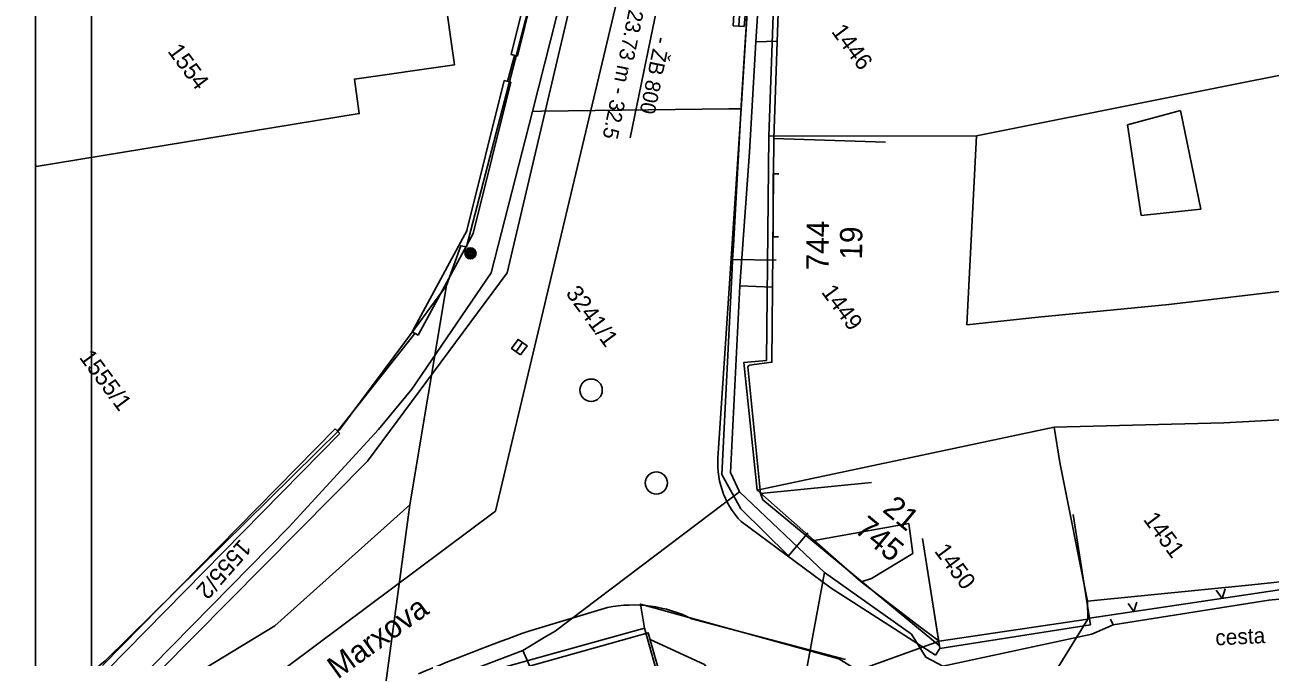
# Model space of a CAD drawing. Extents: x -601580 to 4, y -1204314 to 4.
# Drawn here: x -596076.5 to -596020.7, y -1203028.4 to -1203000.1 of the extents above; entities that cross this region are included whole.
import ezdxf

# ---------------------------------------------------------------- set-up
doc = ezdxf.new("R2010")
doc.units = 0
for name, color, linetype in [('00-INNOGY-STL', 7, 'Continuous'), ('00-KN-HRANICE PARCEL', 7, 'Continuous'), ('00-KN-PARC. CISLA', 7, 'Continuous'), ('00-KN-VNITRNI KRESBA', 7, 'Continuous'), ('00-POLOHOPIS', 7, 'Continuous'), ('00-RAZÍTKO', 7, 'Continuous'), ('00-SITE KOM. KABEL', 7, 'Continuous'), ('00-VAK-KANAL-POPIS', 7, 'Continuous'), ('00-VAK-KANAL-POTRUBI', 7, 'Continuous'), ('00-VAK-VODA-RAD IGIS', 7, 'Continuous'), ('Vrstva 25', 7, 'Continuous'), ('Vrstva 27', 7, 'Continuous'), ('Vrstva 6', 7, 'Continuous')]:
    doc.layers.add(name, color=color, linetype=linetype)

# ---------------------------------------------------------------- blocks, each defined once
blk = doc.blocks.new('6.20_34')
at = {"layer": 'Vrstva 27'}
blk.add_circle((0, 0), 0.5, dxfattribs=at)
blk = doc.blocks.new('6.20_36')
at = {"layer": 'Vrstva 27'}
blk.add_circle((0, 0), 0.5, dxfattribs=at)
blk = doc.blocks.new('6.30_32')
at = {"layer": 'Vrstva 27'}
blk.add_line((-0.25, 0), (0.25, 0), dxfattribs=at)
blk.add_lwpolyline([(-0.25, -0.25), (0.25, -0.25), (0.25, 0.25), (-0.25, 0.25)], close=True, dxfattribs=at)
blk = doc.blocks.new('6.30_36')
at = {"layer": 'Vrstva 27'}
blk.add_line((-0.25, 0), (0.25, 0), dxfattribs=at)
blk.add_lwpolyline([(-0.25, -0.249), (0.249, -0.25), (0.25, 0.249), (-0.249, 0.25)], close=True, dxfattribs=at)
blk = doc.blocks.new('6.01A_948')
at = {"layer": 'Vrstva 25'}
for radius in [0.25, 0.2, 0.15, 0.1, 0.05]:
    blk.add_circle((0, 0), radius, dxfattribs=at)
blk = doc.blocks.new('VCHOD_1784')
at = {"layer": 'Vrstva 6'}
blk.add_line((0, 0.25), (0, 0), dxfattribs=at)
blk = doc.blocks.new('VCHOD_1786')
at = {"layer": 'Vrstva 6'}
blk.add_line((0, 0.25), (0, 0), dxfattribs=at)

msp = doc.modelspace()

# ---------------------------------------------------------------- linework, layer by layer
for points in [[(-595970.972, -1202892.468), (-595970.972, -1202889.968), (-596076.023, -1202889.968), (-596076.023, -1203038.468), (-595970.972, -1203038.468), (-595970.972, -1203035.968)], [(-595973.472, -1202892.468), (-596073.523, -1202892.468), (-596073.523, -1203035.968), (-595973.472, -1203035.968)]]:
    msp.add_lwpolyline(points)
at = {"layer": '00-INNOGY-STL'}
msp.add_line((-596044.786, -1203010.608), (-596042.83, -1203010.626), dxfattribs=at)
for points in [[(-596076.023, -1203034.145), (-596064.674, -1203022.605), (-596060.652, -1203018.225), (-596059.161, -1203016.409), (-596055.603, -1203011.202), (-596053.753, -1203003.963), (-596051.597, -1202995.476), (-596051.393, -1202994.341), (-596050.742, -1202990.856), (-596050.738, -1202990.835), (-596049.188, -1202984.024), (-596049.13, -1202983.918), (-596049.061, -1202983.842), (-596046.948, -1202982.697), (-596046.863, -1202982.659), (-596046.815, -1202982.524), (-596045.335, -1202977.689), (-596043.643, -1202967.753), (-596042.334, -1202958.612), (-596041.394, -1202951.724), (-596041.232, -1202950.533), (-596041.005, -1202949.373)], [(-596042.353, -1202992.662), (-596042.645, -1202992.654), (-596043.705, -1202992.619), (-596044.399, -1203003.703), (-596044.409, -1203003.852)], [(-596053.753, -1203003.963), (-596053.359, -1203003.957), (-596044.953, -1203003.857), (-596044.409, -1203003.852)], [(-596044.409, -1203003.852), (-596044.417, -1203004.008), (-596044.751, -1203009.984), (-596044.786, -1203010.608)], [(-596044.786, -1203010.608), (-596044.806, -1203011.034), (-596045.274, -1203020.236), (-596044.424, -1203021.784), (-596042.276, -1203023.889), (-596041.685, -1203023.176), (-596041.415, -1203022.851)]]:
    msp.add_lwpolyline(points, dxfattribs=at)
at = {"layer": '00-KN-HRANICE PARCEL'}
for p, q in [((-596043.16, -1203005.08), (-596042.701, -1202991.638)), ((-596059.256, -1203021.598), (-596057.615, -1203011.762)), ((-596030.379, -1203018.122), (-596022.766, -1203017.926)), ((-596022.766, -1203017.926), (-596017.692, -1203017.647)), ((-596043.691, -1203020.942), (-596030.379, -1203018.122)), ((-596059.256, -1203021.598), (-596060.432, -1203030.367)), ((-596028.879, -1203025.913), (-596028.863, -1203026.723)), ((-596028.863, -1203026.723), (-596035.536, -1203027.716)), ((-596028.863, -1203026.723), (-596031.071, -1203030.292)), ((-596060.432, -1203030.367), (-596048.738, -1203027.129)), ((-596039.175, -1203029.022), (-596035.536, -1203027.716))]:
    msp.add_line(p, q, dxfattribs=at)
for points in [[(-596057.615, -1203011.762), (-596056.967, -1203009.986), (-596056.717, -1203010.037), (-596053.589, -1202998.026), (-596052.638, -1202993.435)], [(-596076.005, -1203006.433), (-596061.523, -1203004.065), (-596061.738, -1203002.518), (-596057.246, -1203001.874), (-596058.195, -1202995.243), (-596076.023, -1202997.797)], [(-596013.132, -1203001.173), (-596017.019, -1203001.692), (-596033.864, -1203005.054), (-596043.16, -1203005.08)], [(-596043.16, -1203005.08), (-596043.266, -1203015.122), (-596044.288, -1203015.221), (-596043.691, -1203020.942)], [(-596076.023, -1203006.312), (-596076.005, -1203006.433)], [(-596076.023, -1203031.127), (-596072.907, -1203028.593), (-596062.412, -1203018.237), (-596059.007, -1203013.68), (-596057.615, -1203011.762)], [(-596030.379, -1203018.122), (-596030.119, -1203019.697), (-596028.879, -1203025.913)], [(-596039.031, -1203025.055), (-596041.136, -1203023.192), (-596043.691, -1203020.942)], [(-596076.504, -1203033.529), (-596075.203, -1203033.049), (-596065.305, -1203027.022), (-596059.256, -1203021.598)], [(-596028.879, -1203025.913), (-596021.51, -1203025.188), (-596017.58, -1203024.761)], [(-596035.536, -1203027.716), (-596036.527, -1203026.969), (-596039.031, -1203025.055)], [(-596039.175, -1203029.022), (-596040.02, -1203028.504), (-596048.92, -1203026.044), (-596048.738, -1203027.129)], [(-596048.738, -1203027.129), (-596047.655, -1203030.97), (-596045.714, -1203038.148), (-596045.608, -1203038.468)]]:
    msp.add_lwpolyline(points, dxfattribs=at)
at = {"layer": '00-KN-VNITRNI KRESBA'}
for p, q in [((-596024.712, -1203003.928), (-596027.093, -1203004.562)), ((-596023.808, -1203008.35), (-596024.712, -1203003.928)), ((-596027.093, -1203004.562), (-596026.48, -1203008.627)), ((-596033.864, -1203005.054), (-596034.296, -1203013.532)), ((-596026.48, -1203008.627), (-596023.808, -1203008.35)), ((-596025.239, -1203012.613), (-596018.343, -1203011.803)), ((-596031.1, -1203013.19), (-596025.239, -1203012.613)), ((-596034.296, -1203013.532), (-596031.1, -1203013.19)), ((-596041.136, -1203023.192), (-596036.884, -1203022.428)), ((-596036.884, -1203022.428), (-596036.705, -1203023.776)), ((-596036.705, -1203023.776), (-596038.559, -1203024.903)), ((-596038.559, -1203024.903), (-596039.031, -1203025.055))]:
    msp.add_line(p, q, dxfattribs=at)
at = {"layer": '00-POLOHOPIS'}
for p, q in [((-596043.41, -1202988.348), (-596044.392, -1203003.626)), ((-596054.714, -1203001.418), (-596052.926, -1202994.164)), ((-596054.423, -1203001.49), (-596052.635, -1202994.236)), ((-596054.894, -1203011.196), (-596051.632, -1202997.343)), ((-596054.88, -1203002.622), (-596054.567, -1203001.454)), ((-596054.714, -1203001.418), (-596054.423, -1203001.49)), ((-596056.708, -1203009.361), (-596055.025, -1203002.587)), ((-596056.416, -1203009.434), (-596054.733, -1203002.659)), ((-596055.025, -1203002.587), (-596054.733, -1203002.659)), ((-596045.428, -1203019.284), (-596044.392, -1203003.626)), ((-596042.975, -1203009.593), (-596042.971, -1203006.764)), ((-596059.147, -1203013.851), (-596056.68, -1203009.291)), ((-596058.883, -1203013.994), (-596056.416, -1203009.434)), ((-596061.155, -1203019.641), (-596054.894, -1203011.196)), ((-596062.499, -1203018.29), (-596059.022, -1203013.918)), ((-596059.147, -1203013.851), (-596058.883, -1203013.994)), ((-596073.029, -1203028.801), (-596062.602, -1203018.188)), ((-596072.815, -1203029.012), (-596062.389, -1203018.398)), ((-596062.602, -1203018.188), (-596062.389, -1203018.398)), ((-596070.476, -1203029.047), (-596061.155, -1203019.641)), ((-596043.425, -1203021.379), (-596043.544, -1203021.094)), ((-596040.375, -1203025.333), (-596044.404, -1203022.348)), ((-596035.691, -1203028.334), (-596040.372, -1203025.326)), ((-596053.923, -1203027.254), (-596050.392, -1203026.198)), ((-596046.614, -1203026.702), (-596039.726, -1203028.53)), ((-596035.502, -1203028.039), (-596035.691, -1203028.334))]:
    msp.add_line(p, q, dxfattribs=at)
for points in [[(-596037.935, -1203005.346), (-596042.932, -1203005.175), (-596042.47, -1202991.715), (-596037.473, -1202991.886)], [(-596038.568, -1203020.6), (-596043.544, -1203021.094), (-596044.108, -1203015.415), (-596044.108, -1203015.415), (-596044.04, -1203015.342), (-596043.029, -1203015.209), (-596042.932, -1203005.175), (-596037.935, -1203005.346)], [(-596036.282, -1203023.101), (-596035.519, -1203027.914), (-596043.425, -1203021.379), (-596043.425, -1203021.379), (-596043.544, -1203021.094), (-596038.568, -1203020.6)], [(-596029.529, -1203022.033), (-596028.749, -1203026.972), (-596035.502, -1203028.039), (-596035.502, -1203028.039), (-596036.282, -1203023.101)], [(-596028.787, -1203026.683), (-596017.375, -1203024.976)], [(-596023.109, -1203025.429), (-596022.852, -1203025.795), (-596022.715, -1203025.37)], [(-596027.066, -1203026.021), (-596026.808, -1203026.386), (-596026.67, -1203025.962)], [(-596058.349, -1203036.631), (-596060.184, -1203030.587), (-596048.565, -1203027.334), (-596047.217, -1203032.149)], [(-596048.48, -1203027.637), (-596046.051, -1203028.748), (-596045.767, -1203029.143)]]:
    msp.add_lwpolyline(points, dxfattribs=at)
for centre, radius, start, end in [((-596041.671, -1203019.732), 3.783, 173.2044, 223.747), ((-596049.247, -1203032.025), 5.938, 63.6861, 101.1217), ((-596011.884, -1203142.942), 123.089, 109.9702, 112.43593)]:
    msp.add_arc(centre, radius, start, end, dxfattribs=at)
at = {"layer": '00-RAZÍTKO'}
for points in [[(-596076.023, -1202889.968), (-595760.871, -1202889.968), (-595760.871, -1203038.468), (-596076.023, -1203038.468)], [(-596073.523, -1202892.468), (-595763.371, -1202892.468), (-595763.371, -1203035.968), (-596073.523, -1203035.968)]]:
    msp.add_lwpolyline(points, close=True, dxfattribs=at)
at = {"layer": '00-SITE KOM. KABEL'}
for points in [[(-596043.749, -1203000.847), (-596043.213, -1202992.392), (-596043.042, -1202989.401), (-596042.271, -1202987.47), (-596036.186, -1202983.402), (-596035.729, -1202980.411), (-596035.406, -1202976.534), (-596035.052, -1202973.656), (-596034.996, -1202972.792)], [(-596043.749, -1203000.847), (-596043.213, -1202992.392), (-596043.042, -1202989.401), (-596042.271, -1202987.47), (-596036.186, -1202983.402), (-596035.729, -1202980.411), (-596035.406, -1202976.534), (-596035.052, -1202973.656), (-596034.996, -1202972.792)], [(-596044.465, -1203011.778), (-596044.03, -1203005.788), (-596043.749, -1203000.847)], [(-596044.465, -1203011.778), (-596044.03, -1203005.788), (-596043.749, -1203000.847)], [(-596043.749, -1203000.847), (-596042.793, -1203000.81)], [(-596044.875, -1203020.152), (-596044.465, -1203011.778)], [(-596044.875, -1203020.152), (-596044.465, -1203011.778)], [(-596044.465, -1203011.778), (-596043.002, -1203011.837)], [(-596044.481, -1203021.018), (-596044.875, -1203020.152)], [(-596044.481, -1203021.018), (-596044.875, -1203020.152)], [(-596054.189, -1203028.124), (-596053.154, -1203027.505), (-596052.738, -1203027.259), (-596044.481, -1203021.018)], [(-596054.189, -1203028.124), (-596053.154, -1203027.505), (-596052.738, -1203027.259), (-596044.481, -1203021.018)], [(-596052.738, -1203027.259), (-596044.481, -1203021.018)], [(-596044.481, -1203021.018), (-596040.663, -1203024.635)], [(-596041.629, -1203029.81), (-596040.663, -1203024.635)], [(-596027.737, -1203026.983), (-596028.691, -1203027.392), (-596035.372, -1203028.827), (-596036.134, -1203028.421), (-596036.775, -1203027.39), (-596040.663, -1203024.635)], [(-595994.943, -1203025.208), (-596001.268, -1203025.244), (-596005.474, -1203025.602), (-596006.596, -1203025.264), (-596008.734, -1203025.219), (-596010.111, -1203025.445), (-596017.207, -1203025.531), (-596020.761, -1203025.878), (-596027.737, -1203026.983)], [(-596027.855, -1203026.722), (-596027.737, -1203026.983)], [(-596071.237, -1203038.468), (-596070.739, -1203038.142), (-596067.981, -1203036.119), (-596060.232, -1203030.418), (-596057.371, -1203029.34), (-596054.189, -1203028.124)], [(-596071.237, -1203038.468), (-596070.739, -1203038.142), (-596067.981, -1203036.119), (-596060.232, -1203030.418), (-596057.371, -1203029.34), (-596054.189, -1203028.124)], [(-596054.189, -1203028.124), (-596053.888, -1203028.797)]]:
    msp.add_lwpolyline(points, dxfattribs=at)
at = {"layer": '00-VAK-KANAL-POTRUBI'}
msp.add_line((-596049.384, -1203005.156), (-596046.81, -1202992.646), dxfattribs=at)
at = {"layer": '00-VAK-VODA-RAD IGIS'}
msp.add_lwpolyline([(-596049.089, -1202995.309), (-596055.412, -1203021.877), (-596068.097, -1203031.349)], dxfattribs=at)

# ---------------------------------------------------------------- block references
at = {"layer": '00-POLOHOPIS'}
for name, p, xscale, yscale, rotation in [('6.30_36', (-596044.495, -1202999.894), 1.0000013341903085, 1.000001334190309, 86.01927135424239), ('VCHOD_1784', (-596042.971, -1203006.764), 0.99999905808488, 0.99999905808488, -90.07785840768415), ('VCHOD_1786', (-596042.975, -1203009.593), 0.99999905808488, 0.99999905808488, -90.07785840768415), ('6.01A_948', (-596056.534, -1203010.328), 0.9999999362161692, 0.9999999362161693, 43.26790920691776), ('6.30_32', (-596054.346, -1203014.53), 1.0000002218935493, 1.0000002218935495, 54.45581572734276)]:
    msp.add_blockref(name, p, dxfattribs=dict(at, xscale=xscale, yscale=yscale, rotation=rotation))
at = {"layer": '00-POLOHOPIS', "rotation": -143.41468170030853}
for name, p in [('6.20_36', (-596051.129, -1203016.461)), ('6.20_34', (-596048.205, -1203020.618))]:
    msp.add_blockref(name, p, dxfattribs=at)

# ---------------------------------------------------------------- texts
at = {"layer": '00-KN-PARC. CISLA'}
for s, rotation, p in [('1446', 306.5853, (-596040.39, -1203000.39)), ('1554', 306.5853, (-596070.135, -1203001.272)), ('3241/1', 306.5853, (-596052.293, -1203012.121)), ('1449', 306.5853, (-596040.838, -1203012.067)), ('1555/1', 306.5853, (-596074.097, -1203014.993)), ('1451', 306.5853, (-596026.412, -1203022.258)), ('1555/2', 228.5853, (-596066.848, -1203023.096)), ('1450', 306.5853, (-596035.772, -1203023.675))]:
    msp.add_text(s, height=0.75, rotation=rotation, dxfattribs=at).set_placement(p)
at = {"layer": '00-POLOHOPIS'}
for s, height, rotation, p in [('744', 1, 89.4425, (-596040.489, -1203011.097)), ('19', 1, 89.4425, (-596038.984, -1203010.614)), ('21', 1, 320.4248, (-596038.116, -1203021.875)), ('745', 1, 320.4248, (-596039.368, -1203022.787)), ('Marxova', 1, 35.8317, (-596062.485, -1203029.434)), ('cesta', 0.7, 2.7704, (-596023.138, -1203027.901))]:
    msp.add_text(s, height=height, rotation=rotation, dxfattribs=at).set_placement(p)
at = {"layer": '00-VAK-KANAL-POPIS'}
for s, height, p in [('23.73 m - 32.5', 0.68241, (-596049.434, -1202999.365)), ('- ŽB 800', 0.6824, (-596048.25, -1203000.576))]:
    msp.add_text(s, height=height, rotation=258.3742, dxfattribs=at).set_placement(p)

doc.saveas('drawing.dxf')
